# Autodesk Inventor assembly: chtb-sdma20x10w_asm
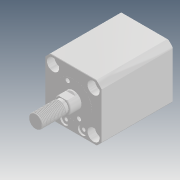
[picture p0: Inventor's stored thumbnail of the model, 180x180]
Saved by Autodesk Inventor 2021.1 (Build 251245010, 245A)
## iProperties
Company: Microsoft
Created: 2018-05
Part Number: chtb-sdma20x10w_asm
Description: STEP AP214
Document SubType Name: Assembly
Designer: user
Title: chtb-sdma20x10w_asm.STEP
Author: Windows
Revision Number: ÈÎºÎ
Sending System: SolidWorks 2015
Preprocessor: SwSTEP 2.0
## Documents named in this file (4)
- D:\Vault_2016\Projekty\Clamptek\Hydraulic\CHTB\CHTB-20\Inventor\CHTB-SDMA20x10W\chtb-sdma20x10w_asm.iam
- D:\Vault_2016\Projekty\Clamptek\Hydraulic\CHTB\CHTB-20\Inventor\CHTB-SDMA20x10W\CHTB-SDMA20X10NBT.ipt
- D:\Vault_2016\Projekty\Clamptek\Hydraulic\CHTB\CHTB-20\Inventor\CHTB-SDMA20x10W\CHTB-SDMA20X10WHSG.ipt
- D:\Vault_2016\Projekty\Clamptek\Hydraulic\CHTB\CHTB-20\Inventor\CHTB-SDMA20x10W\QG_3.ipt
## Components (3 placed, 3 different names)
1. CHTB-SDMA20X10NBT_1
2. CHTB-SDMA20X10WHSG_2
3. QG_3_3
